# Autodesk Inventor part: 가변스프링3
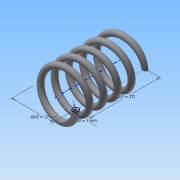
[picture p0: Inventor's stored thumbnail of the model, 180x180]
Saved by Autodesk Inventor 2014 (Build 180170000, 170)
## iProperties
Created: 2015-09
Part Number: 가변스프링3
Material: Generic
Document SubType Name: Modeling
Designer: study
Density: 1 g/cm^3
Appearance: Default
Author: study
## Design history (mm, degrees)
sketch "스케치1"
  geometry: L1 (0, 0)-(11, 0); L2 (11, 0)-(11, 37); L3 (11, 37)-(0, 37); L4 (0, 37)-(0, 0); C1 r 1.5 at (11, 0)
  constraints: 8 end point, 2 parallel, 1 centre point, 1 coincident, 1 horizontal, 1 perpendicular
  dimensions: "d0" = 3 diameter of C1; "d2" = 22 diameter of L2 L4; "d3" = 37 distance of L1.end L2.end (derived)
feature "코일1" sketch "스케치1" pitch "d4" = 10; turns "d6" = 5; dims "d5" = 37 (= d3), "d7" = 0, angle "d8" = 90 deg, angle "d9" = 90 deg, "d10" = 0, "d11" = 0
node "작업 평면1"
sketch "스케치2"
  geometry: L1 (-12.5, 0)-(-9.5, 0) reference; 1 further point
  constraints: 1 horizontal alignment
extrude "돌출1" cut sketch "스케치2" stored distance "d13" = 10; taper "d14" = 0 deg
node "작업 평면2"
sketch "스케치3"
  geometry: L1 (-9.5, 0)-(-12.5, 0) reference; 1 further point
  constraints: 1 horizontal alignment
extrude "돌출2" cut sketch "스케치3" stored distance "d16" = 10; taper "d17" = 0 deg
node "솔리드1"
node "절단 모서리 투영1"
node "절단 모서리 투영2"
other parameters: "d12" = 0, "d15" = 37 (= d3)
